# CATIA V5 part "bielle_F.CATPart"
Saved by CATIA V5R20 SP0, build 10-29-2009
Part number: bielle_F
Bounding box of the stored display mesh (mm): x -30 to 34.77, y 7 to 25, z 77.679 to 87.797
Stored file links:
  D:\Dropbox\IAO_2012\IAO_2012_786_mcamard\mcamard\mcamard\IAO_2012_INI_mcamard_Catia\bielle_F.CATPart
  C:\Users\Matthieu\Desktop\IAO_Artobolevsky\Artobolevsky_786.CATProduct
  D:\Dropbox\IAO_2012\IAO_2012_786_mcamard\mcamard\mcamard\IAO_2012_INI_mcamard_Catia\bielle_BD.CATPart
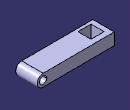
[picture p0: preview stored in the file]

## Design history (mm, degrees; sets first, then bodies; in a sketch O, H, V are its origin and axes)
Set1
  Plane1: linked copy from another document
  Point1 "F": linked copy from another document
  DatumCurve1 to DatumCurve4: linked copy from another document
Body1 (main body)
  Sketch1 on Plane1, origin (0, 0, 0), H (-1, 0, 0), V (0, 0, 1)
    construction line L1 (-29.7792, 82.6787) -> (30.2208, 82.6787)
    point P1 (-29.7792, 82.6787)
    line L2 (-29.7792, 87.6787) -> (-29.7842, 87.6787)
    line L3 (-29.7743, 77.6787) -> (-29.7792, 77.6787)
    arc A1 centre (-29.7792, 82.6787) radius 5 from (-29.7792, 77.6787) to (-29.7792, 87.6787) cw
    circle A2 centre (-29.7792, 82.6787) radius 3
    line L4 (-29.7842, 87.6787) -> (30, 87.7966)
    line L5 (-29.7743, 77.6787) -> (30, 77.7966)
    line L6 (30, 87.7966) -> (30, 77.7966)
    reference projected point E1 (-29.7792, 82.6787) from Point1
    distance L1 L2 = 5
    horizontal: L1 H
    tangency: A1 L2, A1 L3, L4 A1, L5 A1
    vertical: L6 V
    coincidence: P1 E1
  Pad1: profile Sketch1, direction (0, 1, 0), length 25, opposite side length -7
  Sketch2 on face of Pad1 from Sketch1.L4, origin (0.173, 0, 87.7371), H (0, 1, 0), V (-1, 0, 0.002)
    line L1 (9.5, 26.1506) -> (20.5, 26.1506)
    line L2 (20.5, 26.1506) -> (20.5, 15.1506)
    line L3 (20.5, 15.1506) -> (9.5, 15.1506)
    line L4 (9.5, 15.1506) -> (9.5, 26.1506)
    reference projected line E1 (10, 15.6506) -> (20, 15.6506) from edge of DatumCurve2
    reference projected line E2 (10, 25.6506) -> (20, 25.6506) from DatumCurve1
    reference projected line E3 (20, 25.6506) -> (20, 15.6506) from edge of DatumCurve3
    reference projected line E4 (10, 25.6506) -> (10, 15.6506) from edge of DatumCurve4
    distance L3 E1 = 0.5
    distance L1 E2 = 0.5
    distance L2 E3 = 0.5
    distance L4 E4 = 0.5
    horizontal: L1 H, L3 H
    vertical: L2 V, L4 V
  Pocket1: profile Sketch2, direction (-0.002, 0, -1), through (limit type 6)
